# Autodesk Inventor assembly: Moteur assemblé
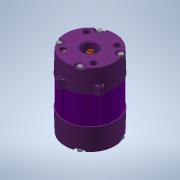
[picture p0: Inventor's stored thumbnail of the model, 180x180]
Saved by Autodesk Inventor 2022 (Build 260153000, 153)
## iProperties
Created: 2005-01
Part Number: Moteur assemblé
Document SubType Name: Assembly
Designer: lolo (Laurent Moretti)
Control State: 0
Master: False
Checked Out: False
Shininess: 64.0
Length Units: 11269
Angle Units: 11279
Time Units: 11290
Mass Units: 11283
Length Display Precision: 3
Angle Display Precision: 2
Compacted: True
Density: 0.0
Volumn: 0.0
Area: 0.0
PropertySet Name: Model Information
Author: lolo (Laurent Moretti)
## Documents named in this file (8)
- C:\Travail\Moteur électrique\Moteur assemblé.iam
- C:\Travail\Moteur électrique\Stator\Stator.iam
- C:\Travail\Moteur électrique\Rotor avec roulements\Rotor avec roulements.iam
- C:\Travail\Moteur électrique\Flasque Avant (coté pompe).ipt
- C:\Travail\Moteur électrique\Flasque Arrière.ipt
- C:\Travail\Moteur électrique\Manchon.ipt
- C:\Travail\Moteur électrique\Vis d'assemblage.ipt
- C:\Travail\Moteur électrique\Ecrou HM4 (moteur).ipt
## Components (14 placed, 7 different names)
1. Stator:1 [sub-assembly] — Placage:1, Placage:8, Placage:10, Placage:11
2. Rotor avec roulements:1 [sub-assembly] — Placage:1, Placage:6, Placage:7, Placage:9
3. Flasque Avant (coté pompe):1 — Placage:4, Placage:5, Placage:8, Logement:1
4. Flasque Arrière:1 — Placage:2, Placage:3, Placage:10, Placage:12, Logement:2
5. Manchon:1 — Placage:4, Placage:5, Placage:6, Placage:7
6. Manchon:2 — Placage:2, Placage:3, Placage:9
7. Vis d'assemblage:1 — Logement:1, Placage:11, Placage:12
8. ISO 4032  (Taraudage usuel) M4:1 — Logement:2
9. Vis d'assemblage:2
10. ISO 4032  (Taraudage usuel) M4:2
11. Vis d'assemblage:3
12. ISO 4032  (Taraudage usuel) M4:3
13. Vis d'assemblage:4
14. ISO 4032  (Taraudage usuel) M4:4
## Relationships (14: Mate 12, Insert 2)
- Placage:1 [Mate]: Stator:1 ↔ Rotor avec roulements:1
- Placage:2 [Mate]: Flasque Arrière:1 ↔ Manchon:2
- Placage:3 [Mate]: Flasque Arrière:1 ↔ Manchon:2
- Placage:4 [Mate]: Flasque Avant (coté pompe):1 ↔ Manchon:1
- Placage:5 [Mate]: Flasque Avant (coté pompe):1 ↔ Manchon:1
- Placage:6 [Mate]: Rotor avec roulements:1 ↔ Manchon:1
- Placage:7 [Mate]: Rotor avec roulements:1 ↔ Manchon:1
- Placage:8 [Mate]: Stator:1 ↔ Flasque Avant (coté pompe):1
- Placage:9 [Mate]: Rotor avec roulements:1 ↔ Manchon:2
- Placage:10 [Mate]: Stator:1 ↔ Flasque Arrière:1
- Logement:1 [Insert]: Flasque Avant (coté pompe):1 ↔ Vis d'assemblage:1
- Placage:11 [Mate]: Stator:1 ↔ Vis d'assemblage:1
- Placage:12 [Mate]: Flasque Arrière:1 ↔ Vis d'assemblage:1
- Logement:2 [Insert]: Flasque Arrière:1 ↔ ISO 4032  (Taraudage usuel) M4:1
